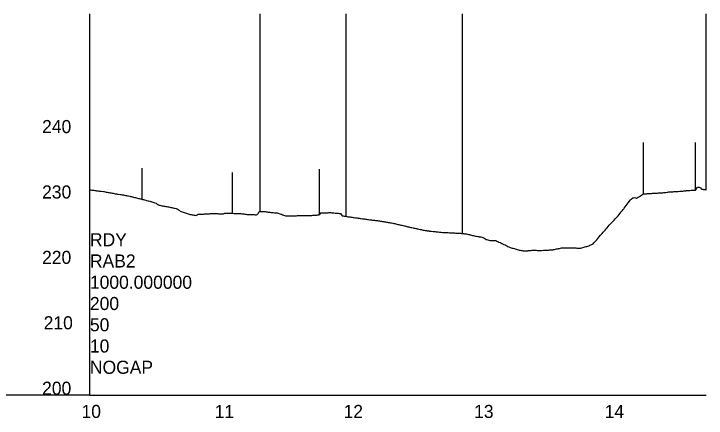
# Model space of a CAD drawing. Extents: x 2115752 to 2121174, y 562881 to 567245.
# Drawn here: x 2120064 to 2120594, y 564619 to 564928 of the extents above; entities that cross this region are included whole.
import ezdxf

# ---------------------------------------------------------------- set-up
doc = ezdxf.new("R2010")
doc.units = 0
for name, color, linetype in [('Exist Profile Cell', 7, 'Continuous'), ('Exist Vertical Profile Ground Line', 7, 'Continuous'), ('Exist Vertical Profile Horizontal Axis Label Major', 7, 'Continuous'), ('Exist Vertical Profile Vertical Axis Label', 7, 'Continuous'), ('Scratch_Level_1', 7, 'Continuous')]:
    doc.layers.add(name, color=color, linetype=linetype)

msp = doc.modelspace()

# ---------------------------------------------------------------- linework, layer by layer
at = {"layer": 'Exist Profile Cell'}
for q in [(2120122.31, 564887.02), (2120593.55, 564637.02), (2120122.31, 564637.02)]:
    msp.add_line((2120122.31, 564637.02), q, dxfattribs=at)
at = {"layer": 'Exist Vertical Profile Ground Line'}
for points in [[(2120122.31, 564793.94), (2120123.08, 564793.84), (2120123.86, 564793.74), (2120124.79, 564793.62), (2120125.41, 564793.53), (2120126.18, 564793.4), (2120126.96, 564793.27), (2120127.38, 564793.19), (2120127.73, 564793.15), (2120128.51, 564793.06), (2120129.28, 564792.97), (2120130.08, 564792.87), (2120130.83, 564792.82), (2120132.61, 564792.63), (2120133.18, 564792.53), (2120133.93, 564792.39), (2120134.7, 564792.24), (2120135.12, 564792.16), (2120135.48, 564792.09), (2120136.36, 564791.94), (2120137.03, 564791.83), (2120137.8, 564791.7), (2120138.61, 564791.57), (2120139.35, 564791.41), (2120140.15, 564791.24), (2120140.9, 564791.1), (2120141.67, 564790.95), (2120142.68, 564790.75), (2120143.22, 564790.68), (2120144, 564790.59), (2120145.55, 564790.4), (2120145.98, 564790.36), (2120146.32, 564790.3), (2120147.1, 564790.16), (2120147.87, 564790.01), (2120148.64, 564789.85), (2120149.42, 564789.69), (2120150.2, 564789.53), (2120150.97, 564789.36), (2120151.74, 564789.19), (2120152.87, 564788.95), (2120153.29, 564788.85), (2120154.07, 564788.68), (2120154.84, 564788.5), (2120155.26, 564788.41), (2120155.66, 564788.32), (2120156.39, 564788.15), (2120157.17, 564787.97), (2120157.94, 564787.78), (2120158.71, 564787.57), (2120159.49, 564787.36), (2120160.26, 564787.17), (2120161.04, 564786.98), (2120161.81, 564786.79), (2120162.59, 564786.6), (2120163.36, 564786.41), (2120164.14, 564786.21), (2120165.1, 564785.96), (2120165.69, 564785.83), (2120166.71, 564785.61), (2120167.23, 564785.47), (2120168.01, 564785.26), (2120168.78, 564785.06), (2120169.09, 564784.97), (2120169.56, 564784.8), (2120170.33, 564784.51), (2120171.11, 564784.23), (2120171.88, 564783.94), (2120172.85, 564783.59), (2120173.43, 564783.24), (2120174.21, 564782.78), (2120175.22, 564782.18), (2120175.76, 564782.07), (2120176.53, 564781.92), (2120177.3, 564781.77), (2120178.08, 564781.63), (2120178.85, 564781.48), (2120179.63, 564781.34), (2120180.4, 564781.2), (2120181.18, 564781.06), (2120181.95, 564780.93), (2120182.73, 564780.8), (2120183.5, 564780.66), (2120184.28, 564780.48), (2120185.05, 564780.31), (2120185.82, 564780.13), (2120186.6, 564779.96), (2120187.37, 564779.79), (2120188.15, 564779.63), (2120189.08, 564779.43), (2120189.7, 564778.91), (2120190.47, 564778.27), (2120191.25, 564777.63), (2120192.02, 564777.34), (2120192.8, 564777.06), (2120193.57, 564776.78), (2120194.35, 564776.51), (2120195.12, 564776.24), (2120195.89, 564775.98), (2120196.67, 564775.72), (2120197.44, 564775.47)], [(2120551.8, 564791.2), (2120552.57, 564791.23), (2120553.64, 564791.27), (2120554.12, 564791.31), (2120554.58, 564791.34), (2120554.89, 564791.36), (2120555.66, 564791.41), (2120556.44, 564791.45), (2120557.21, 564791.5), (2120557.98, 564791.52), (2120558.76, 564791.57), (2120559.53, 564791.61), (2120560.3, 564791.68), (2120561.18, 564791.81), (2120561.89, 564791.9), (2120562.62, 564791.99), (2120563.62, 564792.13), (2120564.29, 564792.19), (2120564.94, 564792.26), (2120565.92, 564792.35), (2120566.49, 564792.39), (2120566.94, 564792.43), (2120567.26, 564792.45), (2120568.03, 564792.49), (2120568.81, 564792.54), (2120569.58, 564792.58), (2120570.35, 564792.63), (2120571.13, 564792.67), (2120571.9, 564792.72), (2120572.21, 564792.74), (2120573.45, 564792.81), (2120574.22, 564792.85), (2120574.99, 564792.9), (2120575.77, 564792.98), (2120576.54, 564793.05), (2120577.31, 564793.14), (2120578.08, 564793.23), (2120578.46, 564793.27), (2120578.86, 564793.29), (2120579.63, 564793.35), (2120580.4, 564793.4), (2120581.18, 564793.45), (2120582.21, 564793.53), (2120582.72, 564793.57), (2120583.5, 564793.63), (2120584.27, 564793.69), (2120585.44, 564793.76), (2120585.82, 564794.37), (2120586.84, 564796.07), (2120587.36, 564795.97), (2120588.14, 564795.93), (2120589.17, 564795.46), (2120589.94, 564794.52), (2120590.57, 564794.38), (2120590.89, 564794.32), (2120591.23, 564794.27), (2120592, 564794.16), (2120592.77, 564794.05), (2120593.55, 564793.94)], [(2120479.57, 564748.78), (2120479.9, 564748.84), (2120480.67, 564748.99), (2120481.44, 564749.14), (2120482.21, 564749.3), (2120482.99, 564749.45), (2120483.76, 564749.61), (2120484.16, 564749.69), (2120484.53, 564749.68), (2120485.31, 564749.67), (2120486.08, 564749.65), (2120486.85, 564749.64), (2120487.63, 564749.64), (2120488.4, 564749.63), (2120489.17, 564749.63), (2120489.95, 564749.63), (2120490.72, 564749.59), (2120491.49, 564749.55), (2120492.27, 564749.51), (2120493.04, 564749.48), (2120493.81, 564749.44), (2120494.58, 564749.42), (2120495.36, 564749.39), (2120496.13, 564749.37), (2120496.9, 564749.35), (2120497.69, 564749.34), (2120498.45, 564749.55), (2120499.22, 564749.77), (2120500, 564749.99), (2120500.77, 564750.22), (2120501.54, 564750.46), (2120502.32, 564750.7), (2120503.09, 564750.95), (2120503.86, 564751.21), (2120504.64, 564751.54), (2120505.41, 564751.87), (2120506.18, 564752.23), (2120507.05, 564752.73), (2120507.73, 564753.39), (2120508.5, 564754.16), (2120509.27, 564754.94), (2120510.05, 564755.75), (2120510.82, 564756.77), (2120511.59, 564757.8), (2120512.66, 564759.23), (2120513.14, 564759.75), (2120513.91, 564760.59), (2120514.69, 564761.45), (2120515.46, 564762.31), (2120516.23, 564763.19), (2120517.01, 564764.08), (2120517.78, 564764.97), (2120518.55, 564765.88), (2120519.33, 564766.79), (2120520.1, 564767.71), (2120520.87, 564768.48), (2120521.65, 564769.25), (2120522.42, 564770.04), (2120523.19, 564770.83), (2120523.96, 564771.63), (2120524.74, 564772.44), (2120525.51, 564773.26), (2120525.81, 564773.59), (2120526.28, 564774.15), (2120527.06, 564775.09), (2120527.83, 564776.03), (2120528.6, 564776.97), (2120529.38, 564777.93), (2120530.15, 564778.89), (2120530.56, 564779.41), (2120530.92, 564779.89), (2120531.7, 564780.92), (2120532.47, 564781.95), (2120533.24, 564783), (2120534.02, 564784.05), (2120534.91, 564785.26), (2120535.56, 564786), (2120536.33, 564786.88), (2120537.38, 564787.67), (2120537.88, 564787.8), (2120538.74, 564788.03), (2120539.43, 564787.84), (2120540.3, 564787.6), (2120540.97, 564788.01), (2120541.99, 564788.59), (2120542.52, 564788.9), (2120543.29, 564789.35), (2120544.07, 564789.79), (2120544.84, 564790.24), (2120545.71, 564790.75), (2120546.39, 564790.79), (2120547.16, 564790.87), (2120548.22, 564790.97), (2120548.82, 564791.02), (2120549.16, 564791.04), (2120549.48, 564791.06), (2120550.25, 564791.11), (2120550.64, 564791.14), (2120551.02, 564791.16), (2120551.39, 564791.18), (2120551.8, 564791.2)], [(2120197.44, 564775.47), (2120198.22, 564775.24), (2120198.99, 564775.11), (2120199.77, 564774.97), (2120200.54, 564774.84), (2120201.32, 564774.71), (2120202.09, 564774.59), (2120202.87, 564774.47), (2120203.75, 564774.33), (2120204.42, 564774.83), (2120205.19, 564775.23), (2120205.96, 564775.27), (2120206.74, 564775.3), (2120207.51, 564775.33), (2120208.31, 564775.37), (2120209.06, 564775.41), (2120209.84, 564775.44), (2120210.61, 564775.48), (2120211.39, 564775.52), (2120212.16, 564775.57), (2120212.94, 564775.61), (2120213.71, 564775.66), (2120214.48, 564775.71), (2120215.26, 564775.76), (2120216.03, 564775.81), (2120216.81, 564775.84), (2120217.58, 564775.8), (2120218.36, 564775.77), (2120219.13, 564775.73), (2120219.91, 564775.7), (2120220.68, 564775.67), (2120221.46, 564775.64), (2120222.23, 564775.61), (2120223.01, 564775.58), (2120223.78, 564775.55), (2120224.22, 564775.53), (2120224.55, 564775.64), (2120225.54, 564775.95), (2120226.1, 564775.99), (2120226.88, 564776.03), (2120227.65, 564776.07), (2120228.03, 564776.07), (2120228.43, 564776.06), (2120229.2, 564776.05), (2120229.57, 564776.04), (2120229.98, 564776.03), (2120230.75, 564776), (2120231.56, 564775.96), (2120232.3, 564775.92), (2120233.07, 564775.89), (2120233.85, 564775.86), (2120234.62, 564775.86), (2120235.1, 564775.86), (2120235.4, 564775.86), (2120236.34, 564775.86), (2120236.95, 564775.79), (2120237.32, 564775.75), (2120237.72, 564775.71), (2120238.5, 564775.63), (2120239.27, 564775.55), (2120240.05, 564775.45), (2120240.82, 564775.34), (2120241.72, 564775.23), (2120242.37, 564775.17), (2120243.14, 564775.11), (2120243.92, 564775.05), (2120244.34, 564775.01), (2120244.69, 564774.99), (2120245.67, 564774.93), (2120246.24, 564774.94), (2120247.02, 564774.95), (2120247.79, 564774.95), (2120248.57, 564774.91), (2120249.71, 564774.89), (2120250.12, 564775), (2120251.02, 564775.77), (2120251.75, 564777.34), (2120252.44, 564777.32), (2120253.21, 564777.3), (2120253.99, 564777.27), (2120254.76, 564777.26), (2120255.54, 564777.25), (2120256.34, 564777.24), (2120257.08, 564777.14), (2120257.86, 564777.04), (2120258.63, 564776.94), (2120259.41, 564776.84), (2120260.18, 564776.75), (2120260.96, 564776.66), (2120261.73, 564776.57), (2120262.5, 564776.5), (2120263.37, 564776.42), (2120264.05, 564776.38), (2120264.83, 564776.34), (2120265.6, 564776.3), (2120266.38, 564776.17), (2120267.44, 564775.68), (2120268.21, 564775.4), (2120268.7, 564775.2), (2120269.47, 564774.9), (2120269.85, 564774.72)], [(2120269.85, 564774.72), (2120270.25, 564774.6), (2120271.34, 564774.25), (2120271.97, 564773.91), (2120272.57, 564773.94), (2120273.04, 564773.96), (2120274.12, 564773.98), (2120274.89, 564774), (2120275.89, 564774.02), (2120276.44, 564774.05), (2120277.25, 564774.08), (2120278.27, 564774.11), (2120278.76, 564774.12), (2120279.81, 564774.14), (2120280.31, 564774.15), (2120281.09, 564774.17), (2120281.87, 564774.18), (2120282.29, 564774.2), (2120282.96, 564774.22), (2120283.41, 564774.22), (2120284.18, 564774.24), (2120285.09, 564774.26), (2120285.73, 564774.25), (2120286.5, 564774.24), (2120287.44, 564774.22), (2120288.05, 564774.25), (2120288.83, 564774.28), (2120289.6, 564774.31), (2120290.07, 564774.33), (2120290.38, 564774.33), (2120291.15, 564774.36), (2120291.92, 564774.38), (2120292.87, 564774.41), (2120293.47, 564774.44), (2120294.25, 564774.48), (2120295.02, 564774.52), (2120295.38, 564774.54), (2120295.8, 564774.59), (2120296.57, 564774.68), (2120296.94, 564774.72), (2120297.34, 564774.77), (2120298.12, 564775.16), (2120298.98, 564776.38), (2120299.67, 564776.39), (2120300.44, 564776.39), (2120301.21, 564776.4), (2120301.99, 564776.4), (2120302.76, 564776.41), (2120303.64, 564776.42), (2120304.31, 564776.43), (2120305.09, 564776.45), (2120305.86, 564776.46), (2120306.63, 564776.46), (2120307.41, 564776.39), (2120308.18, 564776.32), (2120308.96, 564776.25), (2120309.73, 564776.18), (2120310.51, 564776.11), (2120311.28, 564776.04), (2120312.05, 564775.98), (2120312.83, 564775.92), (2120313.87, 564775.83), (2120314.5, 564774.92), (2120315.15, 564774.14), (2120315.47, 564774.08), (2120315.92, 564774), (2120316.7, 564773.86), (2120317.47, 564773.72), (2120318.64, 564773.52), (2120319.02, 564773.47), (2120319.79, 564773.37), (2120320.57, 564773.26), (2120321.34, 564773.15), (2120322.12, 564773.05), (2120322.54, 564772.98), (2120322.89, 564772.93), (2120323.66, 564772.82), (2120324.44, 564772.7), (2120325.29, 564772.58), (2120325.68, 564772.52), (2120325.98, 564772.48), (2120326.76, 564772.39), (2120327.56, 564772.28), (2120328.31, 564772.17), (2120329.08, 564772.05), (2120329.85, 564771.94), (2120330.63, 564771.84), (2120331.4, 564771.73), (2120332.17, 564771.64), (2120332.95, 564771.54), (2120333.72, 564771.45), (2120334.51, 564771.35), (2120335.27, 564771.25), (2120336.36, 564771.09), (2120336.82, 564771.02), (2120337.61, 564770.9), (2120338.36, 564770.78), (2120339.18, 564770.66), (2120339.91, 564770.6), (2120340.68, 564770.53), (2120341, 564770.51)], [(2120341, 564770.51), (2120341.66, 564770.46), (2120342.23, 564770.37), (2120343.01, 564770.26), (2120343.78, 564770.14), (2120344.55, 564770.01), (2120345.4, 564769.88), (2120345.75, 564769.82), (2120346.1, 564769.77), (2120346.87, 564769.65), (2120347.19, 564769.6), (2120347.65, 564769.52), (2120348.02, 564769.45), (2120348.42, 564769.37), (2120349.19, 564769.23), (2120349.97, 564769.1), (2120350.38, 564769.02), (2120351.13, 564768.9), (2120351.52, 564768.84), (2120352.29, 564768.72), (2120353.06, 564768.58), (2120353.84, 564768.41), (2120354.76, 564768.22), (2120355.38, 564768.08), (2120356.32, 564767.87), (2120356.93, 564767.72), (2120357.7, 564767.53), (2120358.48, 564767.34), (2120359.25, 564767.16), (2120360.03, 564766.97), (2120360.48, 564766.87), (2120360.8, 564766.8), (2120361.61, 564766.62), (2120362.58, 564766.4), (2120363.12, 564766.27), (2120363.89, 564766.09), (2120364.29, 564766), (2120364.67, 564765.91), (2120365.53, 564765.7), (2120366.22, 564765.55), (2120366.65, 564765.45), (2120366.99, 564765.37), (2120367.76, 564765.19), (2120368.54, 564765.03), (2120369.44, 564764.84), (2120370.08, 564764.7), (2120370.53, 564764.6), (2120370.86, 564764.52), (2120371.63, 564764.33), (2120372.03, 564764.23), (2120372.65, 564764.11), (2120373.18, 564764.01), (2120373.95, 564763.85), (2120374.95, 564763.66), (2120375.5, 564763.54), (2120376.27, 564763.37), (2120377.15, 564763.18), (2120377.82, 564763.06), (2120378.59, 564762.92), (2120379.59, 564762.75), (2120380.14, 564762.67), (2120380.91, 564762.56), (2120381.37, 564762.49), (2120381.69, 564762.45), (2120382.02, 564762.4), (2120382.46, 564762.35), (2120383.24, 564762.27), (2120384.78, 564762.11), (2120385.56, 564762.03), (2120386.33, 564761.96), (2120387.1, 564761.9), (2120387.88, 564761.81), (2120388.65, 564761.72), (2120389.73, 564761.6), (2120390.2, 564761.54), (2120390.97, 564761.45), (2120391.97, 564761.33), (2120392.52, 564761.3), (2120393.29, 564761.25), (2120394.11, 564761.2), (2120394.53, 564761.21), (2120395.07, 564761.17), (2120395.61, 564761.17), (2120396.39, 564761.17), (2120397.16, 564761.16), (2120397.94, 564761.13), (2120398.71, 564761.09), (2120399.6, 564761.01), (2120400.26, 564760.97), (2120400.65, 564760.95), (2120401.03, 564760.92), (2120401.8, 564760.86), (2120402.16, 564760.83), (2120402.75, 564760.78), (2120403.35, 564760.75), (2120404.12, 564760.73), (2120404.9, 564760.7), (2120405.32, 564760.69), (2120405.67, 564760.67), (2120406.45, 564760.63), (2120407.33, 564760.59)], [(2120407.33, 564760.59), (2120408.25, 564760.41), (2120408.77, 564760.36), (2120409.54, 564760.28), (2120409.96, 564760.23), (2120410.31, 564760.15), (2120411.09, 564759.98), (2120411.86, 564759.8), (2120412.63, 564759.64), (2120413.06, 564759.54), (2120413.4, 564759.45), (2120414.18, 564759.27), (2120414.95, 564759.08), (2120415.3, 564759), (2120415.72, 564758.91), (2120416.5, 564758.74), (2120417.27, 564758.58), (2120418.04, 564758.4), (2120418.88, 564758.25), (2120419.59, 564758.15), (2120420.03, 564758.09), (2120420.36, 564758.03), (2120420.8, 564757.96), (2120421.19, 564757.85), (2120421.91, 564757.72), (2120422.7, 564757.59), (2120423.46, 564757.3), (2120424.23, 564756.65), (2120425, 564756.02), (2120425.78, 564755.81), (2120426.55, 564755.6), (2120427.32, 564755.39), (2120428.13, 564755.17), (2120428.87, 564755.16), (2120429.64, 564755.15), (2120430.41, 564755.15), (2120431.19, 564755.15), (2120431.96, 564755.16), (2120432.74, 564755.16), (2120433.51, 564754.78), (2120434.28, 564754.39), (2120435.05, 564754.01), (2120436.04, 564753.52), (2120436.6, 564753.27), (2120437.37, 564752.92), (2120438.15, 564752.57), (2120438.92, 564752.23), (2120439.85, 564751.82), (2120440.46, 564751.5), (2120441.24, 564751.1), (2120442.01, 564750.7), (2120442.78, 564750.3), (2120443.56, 564749.91), (2120444.33, 564749.59), (2120445.1, 564749.42), (2120445.88, 564749.25), (2120446.92, 564749.03), (2120447.42, 564748.85), (2120448.2, 564748.58), (2120448.97, 564748.32), (2120450.01, 564747.97), (2120450.52, 564747.88), (2120451.29, 564747.75), (2120452.06, 564747.62), (2120452.84, 564747.5), (2120453.61, 564747.38), (2120454.02, 564747.32), (2120454.38, 564747.33), (2120455.15, 564747.34), (2120455.93, 564747.36), (2120456.7, 564747.38), (2120457.15, 564747.4), (2120457.47, 564747.42), (2120458.25, 564747.49), (2120459.02, 564747.56), (2120459.79, 564747.63), (2120460.57, 564747.71), (2120461.34, 564747.77), (2120462.11, 564747.73), (2120462.89, 564747.7), (2120463.66, 564747.67), (2120464.43, 564747.65), (2120465.21, 564747.63), (2120465.98, 564747.62), (2120466.75, 564747.61), (2120467.52, 564747.6), (2120469.07, 564747.67), (2120469.84, 564747.71), (2120470.62, 564747.75), (2120471.39, 564747.79), (2120472.16, 564747.84), (2120472.94, 564747.89), (2120473.71, 564747.94), (2120474.48, 564747.99), (2120475.26, 564748.05), (2120476.18, 564748.12), (2120476.8, 564748.24), (2120477.58, 564748.39), (2120478.35, 564748.54), (2120479.12, 564748.69), (2120479.57, 564748.78)]]:
    msp.add_lwpolyline(points, dxfattribs=at)
at = {"layer": 'Scratch_Level_1'}
for p, q in [((2120122.31, 564637.02), (2120122.31, 564928.42)), ((2120252.44, 564777.32), (2120252.44, 564928.42)), ((2120318.25, 564773.57), (2120318.25, 564928.42)), ((2120407.22, 564760.59), (2120407.22, 564928.42)), ((2120593.55, 564793.94), (2120593.55, 564928.42)), ((2120545.71, 564790.75), (2120545.71, 564830.15)), ((2120585.44, 564793.76), (2120585.44, 564830.15)), ((2120162.29, 564786.68), (2120162.29, 564810.54)), ((2120297.88, 564775.04), (2120297.88, 564809.81)), ((2120231.37, 564775.97), (2120231.37, 564807.2)), ((2120122.31, 564637.02), (2119746.02, 564637.02))]:
    msp.add_line(p, q, dxfattribs=at)

# ---------------------------------------------------------------- texts
at = {"layer": 'Exist Profile Cell'}
for s, p in [('RDY', (2120122.31, 564750.77)), ('RAB2', (2120122.31, 564734.52)), ('1000.000000', (2120122.31, 564718.27)), ('200', (2120122.31, 564702.02)), ('50', (2120122.31, 564685.77)), ('10', (2120122.31, 564669.52)), ('NOGAP', (2120122.31, 564653.27))]:
    msp.add_text(s, height=10, dxfattribs=at).set_placement(p)
at = {"layer": 'Exist Vertical Profile Horizontal Axis Label Major'}
for s, p in [('10', (2120115.89, 564619.52)), ('11', (2120217.73, 564619.52)), ('12', (2120316.28, 564619.52)), ('13', (2120416.11, 564619.52)), ('14', (2120515.96, 564619.52))]:
    msp.add_text(s, height=10, dxfattribs=at).set_placement(p)
at = {"layer": 'Exist Vertical Profile Vertical Axis Label'}
for s, p in [('240', (2120085.74, 564837.27)), ('230', (2120085.74, 564787.27)), ('220', (2120085.74, 564737.27)), ('210', (2120086.94, 564687.27)), ('200', (2120085.74, 564637.27))]:
    msp.add_text(s, height=10, dxfattribs=at).set_placement(p)

doc.saveas('drawing.dxf')
